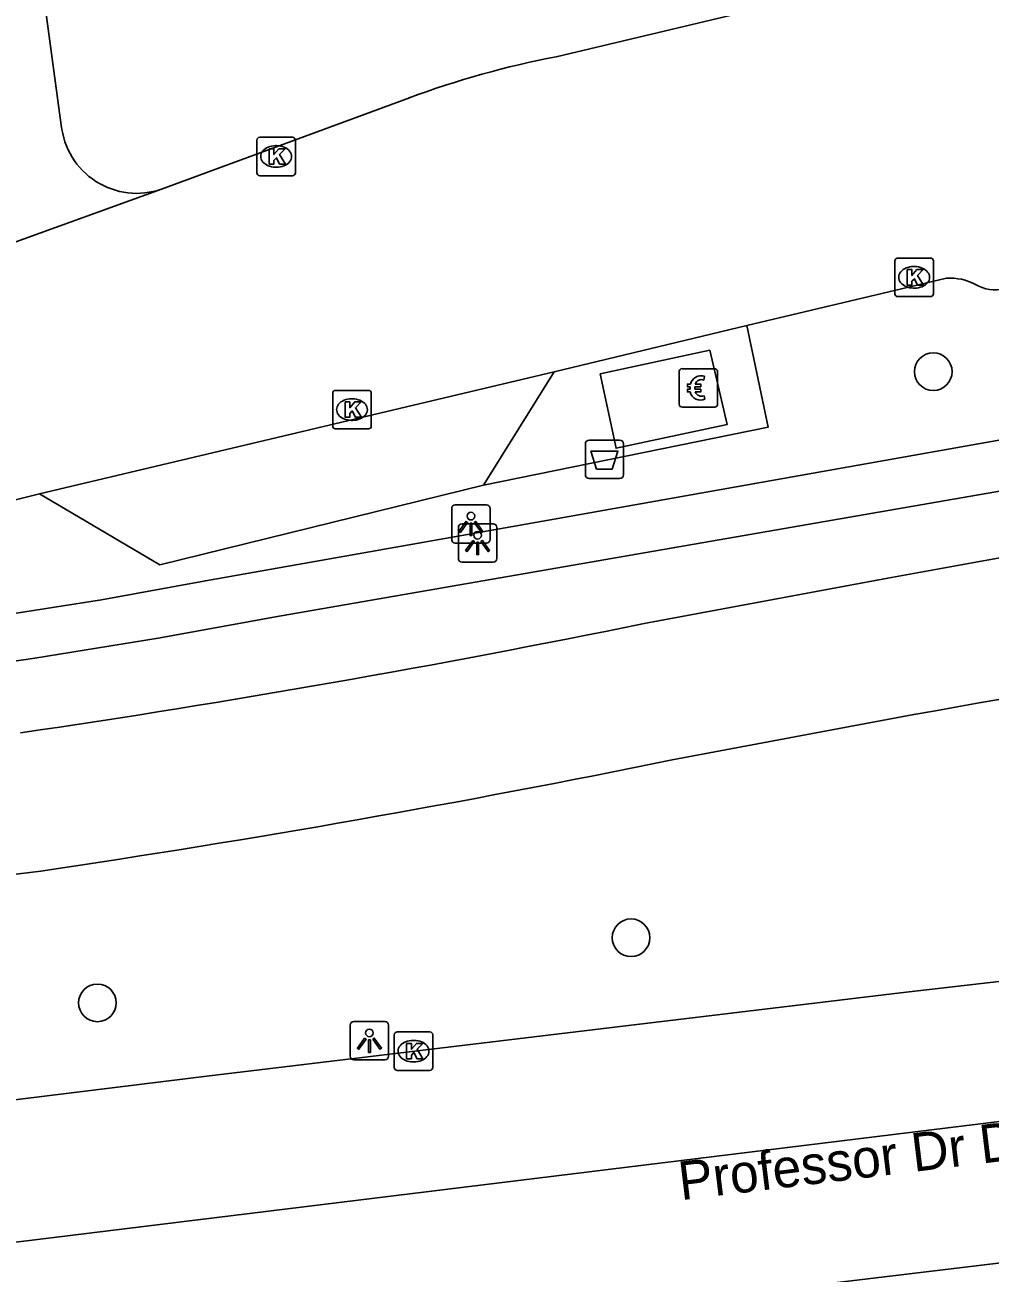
# Model space of a CAD drawing. Extents: x 161477 to 163040, y 383680 to 384868.
# Drawn here: x 162179.52 to 162204.59, y 384070.15 to 384102.58 of the extents above; entities that cross this region are included whole.
import ezdxf

# ---------------------------------------------------------------- set-up
doc = ezdxf.new("R2010")
doc.units = 0
for name, color, linetype in [('IMGEO_Afvalbak', 7, 'Continuous'), ('IMGEO_Betaalautomaat', 7, 'Continuous'), ('IMGEO_Boom', 7, 'Continuous'), ('IMGEO_Fietspad_gesloten', 7, 'Continuous'), ('IMGEO_Haag', 7, 'Continuous'), ('IMGEO_Kolk', 7, 'Continuous'), ('IMGEO_Lichtpunt', 7, 'Continuous'), ('IMGEO_Openbare_ruimte_label', 7, 'Continuous'), ('IMGEO_Parkeervlak_open', 7, 'Continuous'), ('IMGEO_Rijbaan_lokaal_gesloten', 7, 'Continuous'), ('IMGEO_Rijbaan_lokaal_open', 7, 'Continuous'), ('IMGEO_Voetpad_gesloten', 7, 'Continuous'), ('IMGEO_Voetpad_open', 7, 'Continuous')]:
    doc.layers.add(name, color=color, linetype=linetype)

msp = doc.modelspace()

# ---------------------------------------------------------------- linework, layer by layer
at = {"layer": 'IMGEO_Afvalbak'}
for p, q in [((162194.075, 384090.896), (162194.075, 384091.696)), ((162194.075, 384091.696), (162194.075, 384090.896)), ((162194.175, 384091.796), (162194.965, 384091.796)), ((162194.965, 384091.796), (162194.175, 384091.796)), ((162195.065, 384091.696), (162195.065, 384090.896)), ((162195.065, 384090.896), (162195.065, 384091.696)), ((162194.965, 384090.796), (162194.175, 384090.796)), ((162194.175, 384090.796), (162194.965, 384090.796))]:
    msp.add_line(p, q, dxfattribs=at)
msp.add_lwpolyline([(162194.218, 384091.51), (162194.922, 384091.51), (162194.773, 384091.04), (162194.367, 384091.04), (162194.218, 384091.51)], dxfattribs=at)
for centre, start, end in [((162194.175, 384091.696), 90, 180), ((162194.175, 384091.696), 90, 180), ((162194.965, 384091.696), 0, 90), ((162194.965, 384091.696), 360, 90), ((162194.175, 384090.896), 180, 270), ((162194.175, 384090.896), 180, 270), ((162194.965, 384090.896), 270, 0), ((162194.965, 384090.896), 270, 0)]:
    msp.add_arc(centre, 0.1, start, end, dxfattribs=at)
at = {"layer": 'IMGEO_Betaalautomaat'}
for p, q in [((162196.511, 384092.726), (162196.511, 384093.567)), ((162196.511, 384093.567), (162196.511, 384092.726)), ((162196.586, 384093.65), (162197.427, 384093.65)), ((162197.427, 384093.65), (162196.586, 384093.65)), ((162197.51, 384093.576), (162197.51, 384092.735)), ((162197.51, 384092.735), (162197.51, 384093.576)), ((162197.173, 384093.455), (162197.156, 384093.355)), ((162196.794, 384093.114), (162196.794, 384093.182)), ((162196.915, 384093.182), (162196.915, 384093.114)), ((162197.16, 384092.949), (162197.182, 384092.862)), ((162197.436, 384092.651), (162196.595, 384092.651)), ((162196.595, 384092.651), (162197.436, 384092.651))]:
    msp.add_line(p, q, dxfattribs=at)
for points in [[(162196.794, 384093.182), (162196.725, 384093.182), (162196.725, 384093.251), (162196.804, 384093.251)], [(162196.926, 384093.251), (162197.073, 384093.251), (162197.073, 384093.182), (162196.915, 384093.182)], [(162196.799, 384093.045), (162196.725, 384093.045), (162196.725, 384093.114), (162196.794, 384093.114)], [(162196.915, 384093.114), (162197.073, 384093.114), (162197.073, 384093.045), (162196.929, 384093.045)]]:
    msp.add_lwpolyline(points, dxfattribs=at)
for centre, radius, start, end in [((162196.589, 384093.573), 0.0779, 92.4484, 184.2845), ((162196.589, 384093.573), 0.0779, 92.4484, 184.2845), ((162197.433, 384093.573), 0.0779, 2.4484, 94.2845), ((162197.433, 384093.573), 0.0779, 2.4484, 94.2845), ((162197.087, 384093.175), 0.293, 73.014, 165.0139), ((162197.093, 384093.188), 0.179, 69.3236, 159.5683), ((162197.06, 384093.1), 0.267, 191.8096, 297.0389), ((162197.093, 384093.115), 0.179, 202.7625, 291.8693), ((162196.589, 384092.729), 0.0779, 182.4484, 274.2845), ((162196.589, 384092.729), 0.0779, 182.4484, 274.2845), ((162197.433, 384092.729), 0.0779, 272.4484, 4.2845), ((162197.433, 384092.729), 0.0779, 272.4484, 4.2845)]:
    msp.add_arc(centre, radius, start, end, dxfattribs=at)
at = {"layer": 'IMGEO_Boom'}
for centre in [(162203.112, 384093.573), (162195.261, 384078.865), (162181.399, 384077.174)]:
    msp.add_circle(centre, 0.489, dxfattribs=at)
at = {"layer": 'IMGEO_Fietspad_gesloten'}
for points in [[(162201.935, 384088.212), (162195.604, 384087.03)], [(162196.327, 384083.486), (162202.611, 384084.662)], [(161896.962, 384046.212), (161967.373, 384054.741), (162000, 384058.753), (162003.42, 384059.174), (162037.295, 384063.34), (162164.799, 384078.716), (162179.927, 384080.597)]]:
    msp.add_lwpolyline(points, dxfattribs=at)
for centre, radius, start, end in [((162272.264, 383703.099), 391.482, 97.62874, 100.34921), ((162263.288, 383753.375), 336.798, 97.26366, 100.37902), ((162137.256, 384372.163), 291.041, 278.32628, 281.56498), ((162135.05, 384383.345), 306.056, 278.43171, 281.54956)]:
    msp.add_arc(centre, radius, start, end, dxfattribs=at)
at = {"layer": 'IMGEO_Haag'}
for points in [[(162225.641, 384094.843), (162218.982, 384094.181), (162213.494, 384093.304), (162208.018, 384092.361), (162206.327, 384092.061), (162193.115, 384089.718), (162184.206, 384088.139), (162181.503, 384087.646), (162178.788, 384087.217), (162176.065, 384086.851), (162173.334, 384086.55), (162172.924, 384086.511), (162172.515, 384086.473), (162165.347, 384085.474), (162135.742, 384081.906), (162132.946, 384081.569), (162100.634, 384077.733), (162094.619, 384077.023), (162065.523, 384073.587), (162040.402, 384070.402)], [(162040.526, 384069.275), (162094.555, 384075.741), (162128.195, 384079.766), (162135.82, 384080.702), (162167.775, 384084.623), (162170.566, 384084.911), (162173.352, 384085.235), (162176.568, 384085.658), (162179.777, 384086.131), (162182.978, 384086.653), (162186.171, 384087.226), (162205.531, 384090.591), (162209.915, 384091.359), (162214.308, 384092.077), (162218.709, 384092.746), (162223.116, 384093.366), (162224.42, 384093.611), (162225.46, 384092.912)]]:
    msp.add_lwpolyline(points, dxfattribs=at)
at = {"layer": 'IMGEO_Kolk'}
for p, q in [((162185.541, 384098.739), (162185.541, 384099.591)), ((162185.616, 384099.665), (162186.468, 384099.665)), ((162186.029, 384099.445), (162186.054, 384099.445)), ((162186.542, 384099.591), (162186.542, 384098.739)), ((162186.052, 384098.885), (162186.027, 384098.885)), ((162186.468, 384098.665), (162185.616, 384098.665)), ((162202.189, 384096.524), (162203.041, 384096.524)), ((162202.114, 384095.598), (162202.114, 384096.45)), ((162202.602, 384096.304), (162202.627, 384096.304)), ((162203.115, 384096.45), (162203.115, 384095.598)), ((162203.041, 384095.524), (162202.189, 384095.524)), ((162202.625, 384095.744), (162202.6, 384095.744)), ((162187.512, 384092.161), (162187.512, 384093.013)), ((162187.587, 384093.087), (162188.439, 384093.087)), ((162188.513, 384093.013), (162188.513, 384092.161)), ((162188, 384092.867), (162188.025, 384092.867)), ((162188.023, 384092.307), (162187.998, 384092.307)), ((162188.439, 384092.087), (162187.587, 384092.087)), ((162189.186, 384076.419), (162190.038, 384076.419)), ((162189.111, 384075.493), (162189.111, 384076.345)), ((162189.599, 384076.199), (162189.624, 384076.199)), ((162190.112, 384076.345), (162190.112, 384075.493)), ((162190.038, 384075.419), (162189.186, 384075.419)), ((162189.622, 384075.639), (162189.597, 384075.639))]:
    msp.add_line(p, q, dxfattribs=at)
for points in [[(162185.541, 384098.739), (162185.541, 384099.591)], [(162185.616, 384099.665), (162186.468, 384099.665)], [(162186.542, 384099.591), (162186.542, 384098.739)], [(162185.862, 384099.365), (162185.985, 384099.365), (162185.985, 384099.214), (162186.115, 384099.365), (162186.279, 384099.365), (162186.133, 384099.214), (162186.286, 384098.965), (162186.134, 384098.965), (162186.049, 384099.129), (162185.985, 384099.062), (162185.985, 384098.965), (162185.862, 384098.965), (162185.862, 384099.365)], [(162186.468, 384098.665), (162185.616, 384098.665)], [(162202.189, 384096.524), (162203.041, 384096.524)], [(162202.114, 384095.598), (162202.114, 384096.45)], [(162202.435, 384096.224), (162202.558, 384096.224), (162202.558, 384096.073), (162202.688, 384096.224), (162202.852, 384096.224), (162202.706, 384096.073), (162202.859, 384095.824), (162202.707, 384095.824), (162202.622, 384095.988), (162202.558, 384095.921), (162202.558, 384095.824), (162202.435, 384095.824), (162202.435, 384096.224)], [(162203.115, 384096.45), (162203.115, 384095.598)], [(162203.041, 384095.524), (162202.189, 384095.524)], [(162187.512, 384092.161), (162187.512, 384093.013)], [(162187.587, 384093.087), (162188.439, 384093.087)], [(162188.513, 384093.013), (162188.513, 384092.161)], [(162187.833, 384092.787), (162187.956, 384092.787), (162187.956, 384092.636), (162188.086, 384092.787), (162188.25, 384092.787), (162188.104, 384092.636), (162188.257, 384092.387), (162188.105, 384092.387), (162188.02, 384092.551), (162187.956, 384092.484), (162187.956, 384092.387), (162187.833, 384092.387), (162187.833, 384092.787)], [(162188.439, 384092.087), (162187.587, 384092.087)], [(162189.186, 384076.419), (162190.038, 384076.419)], [(162189.111, 384075.493), (162189.111, 384076.345)], [(162189.432, 384076.119), (162189.555, 384076.119), (162189.555, 384075.968), (162189.685, 384076.119), (162189.849, 384076.119), (162189.703, 384075.968), (162189.856, 384075.719), (162189.704, 384075.719), (162189.619, 384075.883), (162189.555, 384075.816), (162189.555, 384075.719), (162189.432, 384075.719), (162189.432, 384076.119)], [(162190.112, 384076.345), (162190.112, 384075.493)], [(162190.038, 384075.419), (162189.186, 384075.419)]]:
    msp.add_lwpolyline(points, dxfattribs=at)
for centre, start, end in [((162185.618, 384099.589), 91.552, 178.448), ((162185.618, 384099.589), 91.552, 178.448), ((162186.466, 384099.589), 1.552, 88.448), ((162186.466, 384099.589), 1.552, 88.448), ((162185.618, 384098.741), 181.552, 268.448), ((162185.618, 384098.741), 181.552, 268.448), ((162186.466, 384098.741), 271.552, 358.448), ((162186.466, 384098.741), 271.552, 358.448), ((162202.191, 384096.448), 91.552, 178.448), ((162202.191, 384096.448), 91.552, 178.448), ((162203.039, 384096.448), 1.552, 88.448), ((162203.039, 384096.448), 1.552, 88.448), ((162202.191, 384095.6), 181.552, 268.448), ((162202.191, 384095.6), 181.552, 268.448), ((162203.039, 384095.6), 271.552, 358.448), ((162203.039, 384095.6), 271.552, 358.448), ((162187.589, 384093.011), 91.552, 178.448), ((162187.589, 384093.011), 91.552, 178.448), ((162188.437, 384093.011), 1.552, 88.448), ((162188.437, 384093.011), 1.552, 88.448), ((162187.589, 384092.163), 181.552, 268.448), ((162187.589, 384092.163), 181.552, 268.448), ((162188.437, 384092.163), 271.552, 358.448), ((162188.437, 384092.163), 271.552, 358.448), ((162189.188, 384076.343), 91.552, 178.448), ((162189.188, 384076.343), 91.552, 178.448), ((162190.036, 384076.343), 1.552, 88.448), ((162190.036, 384076.343), 1.552, 88.448), ((162189.188, 384075.495), 181.552, 268.448), ((162189.188, 384075.495), 181.552, 268.448), ((162190.036, 384075.495), 271.552, 358.448), ((162190.036, 384075.495), 271.552, 358.448)]:
    msp.add_arc(centre, 0.0765, start, end, dxfattribs=at)
for centre, major_axis, ratio, start_param, end_param in [((162186.028, 384099.165), (-0.387, 0.002), 0.722429, 4.712389, 7.853982), ((162186.053, 384099.165), (-0.39, 0.002), 0.717154, 1.570796, 4.712389), ((162202.601, 384096.024), (-0.387, 0.002), 0.722429, 4.712389, 7.853982), ((162202.626, 384096.024), (-0.39, 0.002), 0.717154, 1.570796, 4.712389), ((162187.999, 384092.587), (-0.387, 0.002), 0.722429, 4.712389, 7.853982), ((162188.024, 384092.587), (-0.39, 0.002), 0.717154, 1.570796, 4.712389), ((162189.598, 384075.919), (-0.387, 0.002), 0.722429, 4.712389, 7.853982), ((162189.623, 384075.919), (-0.39, 0.002), 0.717154, 1.570796, 4.712389)]:
    msp.add_ellipse(centre, major_axis=major_axis, ratio=ratio, start_param=start_param, end_param=end_param, dxfattribs=at)
at = {"layer": 'IMGEO_Lichtpunt'}
for p, q in [((162190.603, 384090.021), (162190.603, 384089.214)), ((162190.603, 384090.021), (162190.603, 384089.214)), ((162191.505, 384090.116), (162190.697, 384090.116)), ((162191.505, 384090.116), (162190.697, 384090.116)), ((162191.599, 384089.214), (162191.599, 384090.021)), ((162191.599, 384089.214), (162191.599, 384090.021)), ((162190.777, 384089.526), (162190.777, 384088.719)), ((162190.777, 384089.526), (162190.777, 384088.719)), ((162191.679, 384089.621), (162190.871, 384089.621)), ((162191.679, 384089.621), (162190.871, 384089.621)), ((162191.773, 384088.719), (162191.773, 384089.526)), ((162191.773, 384088.719), (162191.773, 384089.526)), ((162190.697, 384089.12), (162191.505, 384089.12)), ((162190.697, 384089.12), (162191.505, 384089.12)), ((162190.871, 384088.625), (162191.679, 384088.625)), ((162190.871, 384088.625), (162191.679, 384088.625)), ((162188.869, 384076.689), (162188.061, 384076.689)), ((162188.869, 384076.689), (162188.061, 384076.689)), ((162187.967, 384076.594), (162187.967, 384075.787)), ((162187.967, 384076.594), (162187.967, 384075.787)), ((162188.963, 384075.787), (162188.963, 384076.594)), ((162188.963, 384075.787), (162188.963, 384076.594)), ((162188.061, 384075.693), (162188.869, 384075.693)), ((162188.061, 384075.693), (162188.869, 384075.693))]:
    msp.add_line(p, q, dxfattribs=at)
for points in [[(162190.977, 384089.685), (162191.016, 384089.657), (162190.828, 384089.395), (162190.79, 384089.422), (162190.977, 384089.685)], [(162191.189, 384089.657), (162191.227, 384089.684), (162191.414, 384089.422), (162191.375, 384089.394), (162191.189, 384089.657)], [(162191.079, 384089.637), (162191.126, 384089.637), (162191.126, 384089.315), (162191.079, 384089.315), (162191.079, 384089.637)], [(162191.151, 384089.19), (162191.19, 384089.162), (162191.002, 384088.9), (162190.964, 384088.927), (162191.151, 384089.19)], [(162191.253, 384089.142), (162191.3, 384089.142), (162191.3, 384088.82), (162191.253, 384088.82), (162191.253, 384089.142)], [(162191.363, 384089.162), (162191.401, 384089.189), (162191.588, 384088.927), (162191.549, 384088.899), (162191.363, 384089.162)], [(162188.341, 384076.258), (162188.38, 384076.23), (162188.192, 384075.968), (162188.154, 384075.995), (162188.341, 384076.258)], [(162188.443, 384076.21), (162188.49, 384076.21), (162188.49, 384075.888), (162188.443, 384075.888), (162188.443, 384076.21)], [(162188.553, 384076.23), (162188.591, 384076.257), (162188.778, 384075.995), (162188.739, 384075.967), (162188.553, 384076.23)]]:
    msp.add_lwpolyline(points, dxfattribs=at)
for centre in [(162191.102, 384089.819), (162191.276, 384089.324), (162188.466, 384076.392)]:
    msp.add_circle(centre, 0.0994, dxfattribs=at)
for centre, start, end in [((162190.697, 384090.021), 90, 180), ((162190.697, 384090.021), 90, 180), ((162191.505, 384090.021), 0, 90), ((162191.505, 384090.021), 0, 90), ((162190.871, 384089.526), 90, 180), ((162190.871, 384089.526), 90, 180), ((162191.679, 384089.526), 0, 90), ((162191.679, 384089.526), 0, 90), ((162190.697, 384089.214), 180, 270), ((162190.697, 384089.214), 180, 270), ((162191.505, 384089.214), 270, 0), ((162191.505, 384089.214), 270, 360), ((162190.871, 384088.719), 180, 270), ((162190.871, 384088.719), 180, 270), ((162191.679, 384088.719), 270, 0), ((162191.679, 384088.719), 270, 360), ((162188.061, 384076.594), 90, 180), ((162188.061, 384076.594), 90, 180), ((162188.869, 384076.594), 0, 90), ((162188.869, 384076.594), 0, 90), ((162188.061, 384075.787), 180, 270), ((162188.061, 384075.787), 180, 270), ((162188.869, 384075.787), 270, 0), ((162188.869, 384075.787), 270, 360)]:
    msp.add_arc(centre, 0.0946, start, end, dxfattribs=at)
at = {"layer": 'IMGEO_Parkeervlak_open'}
msp.add_lwpolyline([(162179.892, 384090.398), (162183.023, 384088.558), (162191.427, 384090.622)], dxfattribs=at)
at = {"layer": 'IMGEO_Rijbaan_lokaal_gesloten'}
for points in [[(162246.408, 384079.189), (162227.626, 384076.889), (162181.187, 384071.188), (162137.796, 384065.987), (162093.056, 384060.636), (162050.016, 384055.235), (162024.421, 384052.135), (162005.138, 384049.833), (161993.828, 384048.483), (161960.735, 384044.482), (161945.288, 384042.532), (161917.195, 384039.231), (161895.749, 384036.581), (161871.905, 384033.68), (161827.864, 384028.429), (161795.621, 384024.429), (161753.08, 384019.028), (161721.837, 384015.377), (161706.74, 384013.577), (161696.893, 384013.027), (161694.855, 384012.926)], [(162212.301, 384078.633), (162208.493, 384078.157), (162202.261, 384077.434), (162184.31, 384075.274), (162130.338, 384068.624), (162112.945, 384066.661), (162090.69, 384063.861), (162061.99, 384060.529), (162004.465, 384053.494)], [(162005.779, 384046.356), (162186.915, 384068.26), (162246.983, 384075.474)]]:
    msp.add_lwpolyline(points, dxfattribs=at)
at = {"layer": 'IMGEO_Rijbaan_lokaal_open'}
for points in [[(162193.32, 384101.754), (162202.095, 384103.847)], [(162183.068, 384098.316), (162189.503, 384100.686)], [(162171.137, 384093.999), (162183.068, 384098.316)], [(162203.46, 384096), (162198.272, 384094.769)], [(162198.272, 384094.769), (162193.267, 384093.566)], [(162193.267, 384093.566), (162179.892, 384090.398)], [(162179.892, 384090.398), (162167.824, 384087.366), (162165.86, 384086.873), (162163.919, 384086.495), (162151.986, 384084.897), (162137.045, 384083.02), (162126.703, 384081.75), (162074.887, 384075.359), (162049.762, 384072.273), (162040.324, 384071.11)]]:
    msp.add_lwpolyline(points, dxfattribs=at)
for centre, radius, start, end in [((162197.694, 384078.765), 23.402, 100.7737, 110.4897), ((162203.553, 384094.618), 1.385, 61.8233, 93.851), ((162204.737, 384096.74), 1.045, 239.5133, 282.6885)]:
    msp.add_arc(centre, radius, start, end, dxfattribs=at)
at = {"layer": 'IMGEO_Voetpad_gesloten'}
msp.add_lwpolyline([(162194.461, 384093.52), (162197.306, 384094.128), (162197.756, 384092.199), (162194.875, 384091.584), (162194.461, 384093.52)], dxfattribs=at)
at = {"layer": 'IMGEO_Voetpad_open'}
for points in [[(162180.462, 384099.981), (162179.634, 384106.083)], [(162191.427, 384090.622), (162198.827, 384092.133), (162198.272, 384094.769)], [(162193.267, 384093.566), (162191.427, 384090.622)]]:
    msp.add_lwpolyline(points, dxfattribs=at)
msp.add_arc((162182.421, 384100.174), 1.968, 185.6424, 289.2078, dxfattribs=at)

# ---------------------------------------------------------------- texts
at = {"layer": 'IMGEO_Openbare_ruimte_label'}
msp.add_text('Professor Dr Dorgelolaan', height=1, rotation=6.9474, dxfattribs=at).set_placement((162196.557, 384072.045))

doc.saveas('drawing.dxf')
